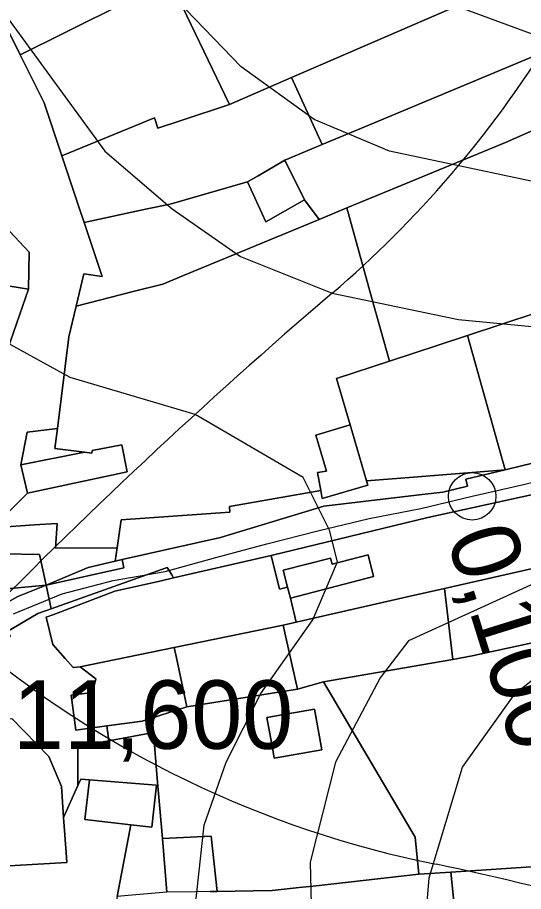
# Model space of a CAD drawing. Extents: x -510989 to -501240, y -1184665 to -1176089.
# Drawn here: x -509446 to -509350, y -1179251.6 to -1179085.6 of the extents above; entities that cross this region are included whole.
import ezdxf

# ---------------------------------------------------------------- set-up
doc = ezdxf.new("R2010")
doc.units = 0
for name, color, linetype in [('NAVRH_rozvodnice', 7, 'Continuous'), ('ostatni_plocha_x_manipulacni_plocha', 7, 'Continuous'), ('ostatni_plocha_x_neplodna_puda', 7, 'Continuous'), ('ostatni_plocha_x_ostatni_komunikace', 7, 'Continuous'), ('ostatni_plocha_x_zelen', 7, 'Continuous'), ('trasovani_toku', 7, 'Continuous'), ('trvaly_travni_porost', 7, 'Continuous'), ('vodni_plocha_x_vodni_tok_v_koryte_umelem', 7, 'Continuous'), ('vrstevnice_01', 7, 'Continuous'), ('vrstevnice_02', 7, 'Continuous'), ('zahrada', 7, 'Continuous'), ('zastavena_plocha_a_nadvori', 7, 'Continuous')]:
    doc.layers.add(name, color=color, linetype=linetype)

msp = doc.modelspace()

# ---------------------------------------------------------------- linework, layer by layer
at = {"layer": 'NAVRH_rozvodnice'}
for centre, radius, start, end in [((-509520.53, -1178981.05), 206.51, 310.5349, 328.1578), ((-508714.16, -1179924.02), 1034.22, 130.53487, 135.81526), ((-509327.48, -1179052.01), 198.3, 229.6773, 258.6338), ((-509437.06, -1179597.15), 357.75, 66.9349, 78.6338)]:
    msp.add_arc(centre, radius, start, end, dxfattribs=at)
at = {"layer": 'ostatni_plocha_x_manipulacni_plocha'}
msp.add_lwpolyline([(-509428.71, -1179222.95), (-509420.22, -1179221.42), (-509419.48, -1179230.16), (-509418.52, -1179241.55), (-509417.66, -1179251.74), (-509425, -1179252.36), (-509427.12, -1179252.54), (-509424.52, -1179238.94), (-509420.55, -1179239.4), (-509419.63, -1179231.41), (-509432.35, -1179230.41), (-509433.99, -1179230.28), (-509434.53, -1179231.48), (-509434.53, -1179223.99)], close=True, dxfattribs=at)
at = {"layer": 'ostatni_plocha_x_neplodna_puda'}
msp.add_lwpolyline([(-509370.08, -1179172.83), (-509353.48, -1179171.5), (-509360.95, -1179173.31), (-509360.63, -1179174.62), (-509365.3, -1179175.75), (-509369.25, -1179176.22), (-509387.89, -1179178.43), (-509407.51, -1179184.4), (-509426.18, -1179188.56), (-509427.46, -1179188.87), (-509427.1, -1179186.33), (-509426.36, -1179181.05), (-509405.73, -1179179.57), (-509405.81, -1179178.49), (-509388.48, -1179175.48), (-509388.21, -1179177), (-509379.51, -1179174.45), (-509379.76, -1179173.61)], close=True, dxfattribs=at)
msp.add_lwpolyline([(-509336.83, -1179187.66), (-509365, -1179194.05), (-509371.51, -1179195.53), (-509393.14, -1179200.44), (-509394.24, -1179195.88), (-509378.43, -1179191.77), (-509379.5, -1179187.64), (-509386.33, -1179189.42), (-509386.63, -1179188.27), (-509395.58, -1179190.6), (-509394.75, -1179193.79), (-509396.3, -1179194.16), (-509397.85, -1179187.79), (-509368.17, -1179180.61), (-509343.61, -1179175.2)], dxfattribs=at)
at = {"layer": 'ostatni_plocha_x_ostatni_komunikace'}
for points in [[(-509449, -1179085.73), (-509445.52, -1179092.72), (-509443.3, -1179097.19), (-509440.98, -1179101.85), (-509437.6, -1179111.93), (-509434.37, -1179121.57), (-509433.38, -1179124.54), (-509429.93, -1179134.83), (-509433.42, -1179134.33), (-509434.87, -1179140.46), (-509436.24, -1179146.26), (-509438.45, -1179163.67), (-509444.2, -1179164.38), (-509445.35, -1179170.55), (-509444.14, -1179175.97), (-509449.3, -1179181.16)], [(-509448.47, -1179150.42), (-509443.93, -1179137.2), (-509443.82, -1179130.22), (-509448.41, -1179125.27)], [(-509448.06, -1179202.28), (-509442.18, -1179198.82), (-509439.64, -1179197.92), (-509417.62, -1179190.06), (-509416.75, -1179191.45), (-509416.39, -1179192.04), (-509418.99, -1179192.64), (-509427.51, -1179194.59), (-509439.12, -1179198.98), (-509440.54, -1179199.52), (-509439.33, -1179204.66), (-509436.94, -1179207.36), (-509435.45, -1179209.05), (-509434.1, -1179208.93), (-509431.15, -1179211.23), (-509431.78, -1179213.78), (-509435.82, -1179214.33), (-509434.93, -1179220.93), (-509429.06, -1179220.14), (-509428.71, -1179222.95), (-509434.53, -1179223.99), (-509434.53, -1179231.48), (-509437.25, -1179237.56), (-509437.67, -1179231.67), (-509440.09, -1179225.97), (-509447.07, -1179218.71)], [(-509448.68, -1179194.16), (-509440.59, -1179193.43), (-509445.97, -1179195.55), (-509451.12, -1179198.47)]]:
    msp.add_lwpolyline(points, dxfattribs=at)
at = {"layer": 'ostatni_plocha_x_zelen'}
msp.add_lwpolyline([(-509438.45, -1179163.67), (-509438.93, -1179167.46), (-509433.32, -1179168.18), (-509445.35, -1179170.55), (-509444.2, -1179164.38)], close=True, dxfattribs=at)
at = {"layer": 'trasovani_toku'}
for p, q in [((-509350.01, -1179174.29), (-509340.29, -1179171.92)), ((-509359.74, -1179176.56), (-509350.01, -1179174.29)), ((-509369.48, -1179178.84), (-509359.74, -1179176.56)), ((-509379.29, -1179180.77), (-509369.48, -1179178.84)), ((-509389.01, -1179183.13), (-509379.29, -1179180.77)), ((-509398.7, -1179185.61), (-509389.01, -1179183.13)), ((-509408.36, -1179188.2), (-509398.7, -1179185.61)), ((-509418, -1179190.86), (-509408.36, -1179188.2)), ((-509427.85, -1179192.54), (-509418, -1179190.86)), ((-509437.53, -1179195.06), (-509427.85, -1179192.54)), ((-509446.76, -1179198.9), (-509437.53, -1179195.06))]:
    msp.add_line(p, q, dxfattribs=at)
msp.add_circle((-509359.74, -1179176.56), 4.5, dxfattribs=at)
at = {"layer": 'trvaly_travni_porost'}
msp.add_lwpolyline([(-509366.17, -1179147.85), (-509360.64, -1179146.03), (-509353.48, -1179171.5), (-509370.08, -1179172.83), (-509379.76, -1179173.61), (-509382.88, -1179163), (-509385.46, -1179154.22), (-509375.45, -1179150.92)], close=True, dxfattribs=at)
at = {"layer": 'vodni_plocha_x_vodni_tok_v_koryte_umelem'}
msp.add_lwpolyline([(-509343.61, -1179175.2), (-509368.17, -1179180.61), (-509397.85, -1179187.79), (-509403.94, -1179189.19), (-509416.39, -1179192.04), (-509416.75, -1179191.45), (-509417.62, -1179190.06), (-509439.64, -1179197.92), (-509440.59, -1179193.43), (-509425.83, -1179190.15), (-509426.18, -1179188.56), (-509407.51, -1179184.4), (-509387.89, -1179178.43), (-509369.25, -1179176.22), (-509365.3, -1179175.75), (-509360.63, -1179174.62), (-509360.95, -1179173.31), (-509353.48, -1179171.5), (-509348.06, -1179170.19)], dxfattribs=at)
for points in [[(-509427.46, -1179188.87), (-509426.18, -1179188.56), (-509425.83, -1179190.15), (-509440.59, -1179193.43), (-509432.61, -1179190.08)], [(-509440.59, -1179193.43), (-509439.64, -1179197.92), (-509442.18, -1179198.82), (-509448.06, -1179202.28), (-509447.34, -1179203.13), (-509448.62, -1179204.23), (-509449.33, -1179203.4), (-509452.89, -1179206.43), (-509457.04, -1179206.26), (-509456.66, -1179197.08), (-509451.8, -1179197.28), (-509451.12, -1179198.47), (-509445.97, -1179195.55)]]:
    msp.add_lwpolyline(points, close=True, dxfattribs=at)
at = {"layer": 'vrstevnice_01'}
for points in [[(-509337.81, -1179119), (-509375.41, -1179111), (-509389.69, -1179105), (-509403.59, -1179095), (-509422.81, -1179075)], [(-509352.81, -1179422), (-509367.09, -1179407), (-509376.31, -1179394), (-509380.81, -1179383), (-509386.59, -1179356), (-509392.09, -1179344), (-509399.81, -1179332), (-509405.81, -1179319), (-509413.31, -1179264), (-509410.59, -1179239), (-509406.41, -1179227), (-509399.81, -1179214), (-509390, -1179200), (-509385.31, -1179189), (-509386.81, -1179183), (-509391.81, -1179173), (-509412.31, -1179161), (-509436, -1179154), (-509450.59, -1179146), (-509461.69, -1179135), (-509470.19, -1179124), (-509496.41, -1179085)], [(-509346.31, -1179357), (-509366.81, -1179288), (-509369, -1179262), (-509367.91, -1179249), (-509361.59, -1179228), (-509351.59, -1179214), (-509340.19, -1179205)]]:
    msp.add_lwpolyline(points, dxfattribs=at)
at = {"layer": 'vrstevnice_02'}
for points in [[(-509247.91, -1179078), (-509299.81, -1179090), (-509327.59, -1179092), (-509345.09, -1179090), (-509361.41, -1179084)], [(-509452.09, -1179080), (-509429.41, -1179111), (-509416.69, -1179122), (-509403.69, -1179131), (-509386.31, -1179138), (-509362.31, -1179143), (-509320.59, -1179147), (-509305.41, -1179150), (-509302.09, -1179152), (-509298.31, -1179163), (-509303.91, -1179173)], [(-509303.91, -1179173), (-509371.81, -1179204), (-509377.19, -1179211), (-509385.69, -1179227), (-509390.5, -1179246), (-509389.91, -1179270), (-509387.41, -1179286), (-509380.5, -1179304), (-509376.09, -1179331), (-509359.41, -1179375), (-509352, -1179386), (-509338.81, -1179399), (-509325, -1179407), (-509310.19, -1179409), (-509302.69, -1179408), (-509288.19, -1179403), (-509268.5, -1179394), (-509253.69, -1179392), (-509242.91, -1179394), (-509234.5, -1179399), (-509233.5, -1179402), (-509234.19, -1179408), (-509239.41, -1179414), (-509271.81, -1179435)]]:
    msp.add_lwpolyline(points, dxfattribs=at)
at = {"layer": 'zahrada'}
for points in [[(-509351.01, -1179048.21), (-509337.05, -1179070.97), (-509336.63, -1179072.15), (-509386.14, -1179093.63), (-509394.01, -1179097.04), (-509405.76, -1179102.14), (-509417.09, -1179078.59), (-509413.88, -1179077.11), (-509397.78, -1179069.71)], [(-509336.63, -1179072.15), (-509331.64, -1179086.16), (-509379.95, -1179106.34), (-509388.18, -1179109.78), (-509394.01, -1179097.04), (-509386.14, -1179093.63)], [(-509331.64, -1179086.16), (-509330.8, -1179088.53), (-509324.71, -1179096.71), (-509353.4, -1179109.37), (-509374.28, -1179118), (-509383.5, -1179121.81), (-509388.75, -1179123.98), (-509391.55, -1179120.25), (-509395.27, -1179112.74), (-509388.18, -1179109.78), (-509379.95, -1179106.34)], [(-509324.71, -1179096.71), (-509313.62, -1179118.71), (-509316.89, -1179120.29), (-509313.81, -1179126.66), (-509310.44, -1179125.02), (-509308.52, -1179128.81), (-509360.64, -1179146.03), (-509366.17, -1179147.85), (-509375.45, -1179150.92), (-509378.81, -1179138.75), (-509383.5, -1179121.81), (-509374.28, -1179118), (-509353.4, -1179109.37)], [(-509457.48, -1179121.32), (-509454.07, -1179125.83), (-509452.28, -1179128.19), (-509448.41, -1179125.27), (-509443.82, -1179130.22), (-509443.93, -1179137.2), (-509449.84, -1179136.28), (-509452.72, -1179133.06), (-509454.58, -1179133.74), (-509459.35, -1179128.32), (-509461.16, -1179126.1)], [(-509360.64, -1179146.03), (-509308.52, -1179128.81), (-509303.01, -1179147.86), (-509302.08, -1179154.08), (-509326.17, -1179159.08), (-509332.52, -1179165.3), (-509348.06, -1179170.19), (-509353.48, -1179171.5)], [(-509454.58, -1179133.74), (-509452.72, -1179133.06), (-509449.84, -1179136.28), (-509443.93, -1179137.2), (-509448.47, -1179150.42), (-509459.59, -1179151.61), (-509468.18, -1179136.32), (-509468.53, -1179135.7), (-509464.11, -1179141.12)], [(-509442.87, -1179181.99), (-509438.49, -1179181.7), (-509438.77, -1179186.4), (-509427.1, -1179186.33), (-509427.46, -1179188.87), (-509432.61, -1179190.08), (-509440.59, -1179193.43), (-509441.82, -1179187.6), (-509448.57, -1179187.49), (-509448.93, -1179182.39)], [(-509448.57, -1179187.49), (-509441.82, -1179187.6), (-509440.59, -1179193.43), (-509448.68, -1179194.16), (-509449.65, -1179187.47)], [(-509336.83, -1179187.66), (-509331.96, -1179200.81), (-509359.71, -1179206.86), (-509363.41, -1179207.51), (-509365, -1179194.05)], [(-509330.51, -1179203.25), (-509317.2, -1179225.62), (-509300.75, -1179236.66), (-509323.69, -1179245.24), (-509363.76, -1179247.9), (-509369.84, -1179248.31), (-509370.57, -1179241.27), (-509387.92, -1179211.79), (-509369.31, -1179208.54), (-509363.41, -1179207.51), (-509359.71, -1179206.86), (-509331.96, -1179200.81)], [(-509416.27, -1179205.26), (-509415.85, -1179207.24), (-509413.89, -1179216.53), (-509422.33, -1179219.23), (-509429.06, -1179220.14), (-509434.93, -1179220.93), (-509435.82, -1179214.33), (-509431.78, -1179213.78), (-509431.15, -1179211.23), (-509434.1, -1179208.93)], [(-509389.65, -1179216.94), (-509388.29, -1179224.67), (-509397.31, -1179226.26), (-509397.65, -1179224.32), (-509398.67, -1179218.52)], [(-509323.69, -1179245.24), (-509300.75, -1179236.66), (-509292.36, -1179257.49), (-509307.98, -1179262.36), (-509326.53, -1179266.76), (-509330.63, -1179266.76), (-509347.44, -1179266.76), (-509354.63, -1179265.94), (-509361.83, -1179267.12), (-509363.76, -1179247.9)], [(-509418.52, -1179241.55), (-509409.28, -1179241.07), (-509408.15, -1179251.58), (-509409.43, -1179251.6), (-509412.19, -1179251.65), (-509417.66, -1179251.74)]]:
    msp.add_lwpolyline(points, close=True, dxfattribs=at)
at = {"layer": 'zastavena_plocha_a_nadvori'}
for points in [[(-509420.13, -1179065.13), (-509413.88, -1179077.11), (-509417.09, -1179078.59), (-509425.13, -1179082.59), (-509437.12, -1179088.55), (-509445.52, -1179092.72), (-509449, -1179085.73), (-509451.31, -1179081.07), (-509450.7, -1179080.77), (-509431.88, -1179071.54), (-509427.08, -1179069.18), (-509426.72, -1179068.97), (-509426, -1179068.55)], [(-509417.09, -1179078.59), (-509405.76, -1179102.14), (-509414.97, -1179105.19), (-509419.35, -1179106.64), (-509420, -1179104.68), (-509437.6, -1179111.93), (-509440.98, -1179101.85), (-509443.3, -1179097.19), (-509445.52, -1179092.72), (-509437.12, -1179088.55), (-509425.13, -1179082.59)], [(-509394.01, -1179097.04), (-509388.18, -1179109.78), (-509395.27, -1179112.74), (-509400.37, -1179115.72), (-509402.34, -1179116.87), (-509417.01, -1179121.06), (-509421.4, -1179121.99), (-509433.38, -1179124.54), (-509434.37, -1179121.57), (-509437.6, -1179111.93), (-509420, -1179104.68), (-509419.35, -1179106.64), (-509414.97, -1179105.19), (-509405.76, -1179102.14)], [(-509395.27, -1179112.74), (-509391.55, -1179120.25), (-509398.91, -1179124.45), (-509402.34, -1179116.87), (-509400.37, -1179115.72)], [(-509402.34, -1179116.87), (-509398.91, -1179124.45), (-509391.55, -1179120.25), (-509388.75, -1179123.98), (-509414.49, -1179134.62), (-509418.43, -1179136.25), (-509424.05, -1179137.69), (-509434.87, -1179140.46), (-509433.42, -1179134.33), (-509429.93, -1179134.83), (-509433.38, -1179124.54), (-509421.4, -1179121.99), (-509417.01, -1179121.06)], [(-509389.43, -1179164.94), (-509382.88, -1179163), (-509379.76, -1179173.61), (-509379.51, -1179174.45), (-509388.21, -1179177), (-509388.48, -1179175.48), (-509389.07, -1179172.05), (-509387.4, -1179171.76)], [(-509431.87, -1179167.89), (-509426.22, -1179166.78), (-509425.21, -1179171.94), (-509444.14, -1179175.97), (-509445.35, -1179170.55), (-509433.32, -1179168.18), (-509431.93, -1179168.35)], [(-509397.85, -1179187.79), (-509396.3, -1179194.16), (-509394.75, -1179193.79), (-509394.24, -1179195.88), (-509393.14, -1179200.44), (-509395.62, -1179201), (-509416.27, -1179205.26), (-509434.1, -1179208.93), (-509435.45, -1179209.05), (-509436.94, -1179207.36), (-509439.33, -1179204.66), (-509440.54, -1179199.52), (-509439.12, -1179198.98), (-509427.51, -1179194.59), (-509418.99, -1179192.64), (-509416.39, -1179192.04), (-509403.94, -1179189.19)], [(-509386.33, -1179189.42), (-509379.5, -1179187.64), (-509378.43, -1179191.77), (-509394.24, -1179195.88), (-509394.75, -1179193.79), (-509395.58, -1179190.6), (-509386.63, -1179188.27)], [(-509365, -1179194.05), (-509363.41, -1179207.51), (-509369.31, -1179208.54), (-509387.92, -1179211.79), (-509392.86, -1179213.14), (-509395.02, -1179203.64), (-509395.62, -1179201), (-509393.14, -1179200.44), (-509371.51, -1179195.53)], [(-509395.62, -1179201), (-509395.02, -1179203.64), (-509392.86, -1179213.14), (-509399.26, -1179214.17), (-509413.89, -1179216.53), (-509415.85, -1179207.24), (-509416.27, -1179205.26)], [(-509392.86, -1179213.14), (-509387.92, -1179211.79), (-509370.57, -1179241.27), (-509369.84, -1179248.31), (-509383.23, -1179249.8), (-509389.93, -1179250.55), (-509392.54, -1179250.84), (-509397.66, -1179251.41), (-509401.28, -1179251.47), (-509408.15, -1179251.58), (-509409.28, -1179241.07), (-509418.52, -1179241.55), (-509419.48, -1179230.16), (-509420.22, -1179221.42), (-509428.71, -1179222.95), (-509429.06, -1179220.14), (-509422.33, -1179219.23), (-509413.89, -1179216.53), (-509399.26, -1179214.17)], [(-509389.65, -1179216.94), (-509398.67, -1179218.52), (-509397.65, -1179224.32), (-509397.31, -1179226.26), (-509388.29, -1179224.67)], [(-509450.12, -1179218.9), (-509447.07, -1179218.71), (-509440.09, -1179225.97), (-509437.67, -1179231.67), (-509437.25, -1179237.56), (-509436.78, -1179244.2), (-509436.64, -1179246.07), (-509452.1, -1179246.98), (-509454.45, -1179244.72), (-509449.79, -1179240.93), (-509450.35, -1179230.73), (-509448.94, -1179230.59)], [(-509433.99, -1179230.28), (-509432.35, -1179230.41), (-509433.22, -1179237.94), (-509424.52, -1179238.94), (-509427.12, -1179252.54), (-509427.65, -1179255.36), (-509428.34, -1179255.38), (-509430.37, -1179255.44), (-509432.34, -1179255.49), (-509436.12, -1179255.67), (-509438.4, -1179255.78), (-509439.66, -1179255.84), (-509442.85, -1179255.99), (-509448.45, -1179256.26), (-509452.59, -1179256.46), (-509454.45, -1179247.12), (-509452.1, -1179246.98), (-509436.64, -1179246.07), (-509436.78, -1179244.2), (-509437.25, -1179237.56), (-509434.53, -1179231.48)], [(-509432.35, -1179230.41), (-509419.63, -1179231.41), (-509420.55, -1179239.4), (-509424.52, -1179238.94), (-509433.22, -1179237.94)]]:
    msp.add_lwpolyline(points, close=True, dxfattribs=at)
for points in [[(-509449.3, -1179181.16), (-509444.14, -1179175.97), (-509425.21, -1179171.94), (-509426.22, -1179166.78), (-509431.87, -1179167.89), (-509431.93, -1179168.35), (-509433.32, -1179168.18), (-509438.93, -1179167.46), (-509438.45, -1179163.67), (-509436.24, -1179146.26), (-509434.87, -1179140.46), (-509424.05, -1179137.69), (-509418.43, -1179136.25), (-509414.49, -1179134.62), (-509388.75, -1179123.98), (-509383.5, -1179121.81), (-509378.81, -1179138.75), (-509375.45, -1179150.92), (-509385.46, -1179154.22), (-509382.88, -1179163), (-509389.43, -1179164.94), (-509387.4, -1179171.76), (-509389.07, -1179172.05), (-509388.48, -1179175.48), (-509405.81, -1179178.49), (-509405.73, -1179179.57), (-509426.36, -1179181.05), (-509427.1, -1179186.33), (-509438.77, -1179186.4), (-509438.49, -1179181.7), (-509442.87, -1179181.99), (-509448.93, -1179182.39)], [(-509409.43, -1179251.6), (-509408.15, -1179251.58), (-509401.28, -1179251.47), (-509397.66, -1179251.41), (-509392.54, -1179250.84), (-509389.93, -1179250.55), (-509383.23, -1179249.8), (-509369.84, -1179248.31), (-509363.76, -1179247.9), (-509361.83, -1179267.12)]]:
    msp.add_lwpolyline(points, dxfattribs=at)

# ---------------------------------------------------------------- texts
at = {"layer": 'trasovani_toku'}
msp.add_text('0,100', height=13, rotation=287.3865, dxfattribs=at).set_placement((-509364.69, -1179184.31))
msp.add_text('11,600', height=13, dxfattribs=at).set_placement((-509446.87, -1179224.5))

doc.saveas('drawing.dxf')
